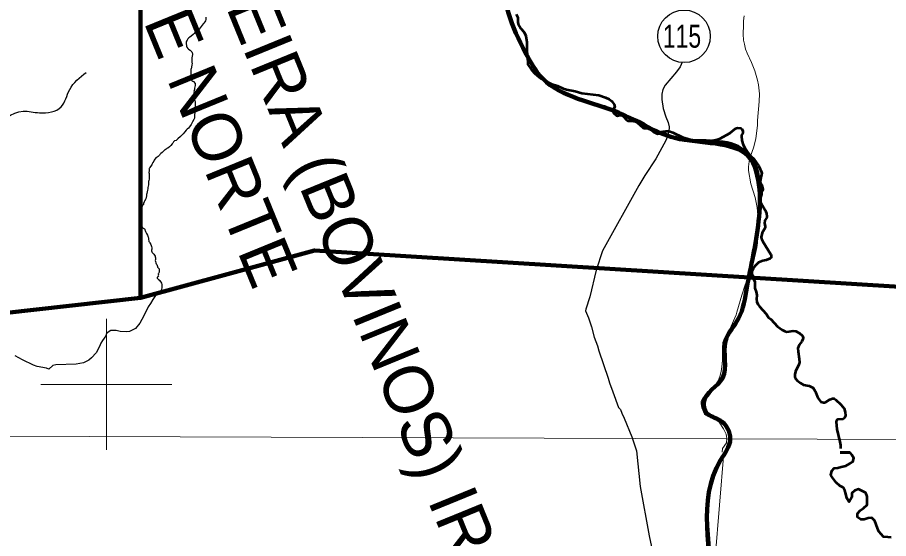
# Model space of a CAD drawing. Extents: x -1643653 to 4543381, y 1624270 to 13878484.
# Drawn here: x 748641 to 761950, y 8947643 to 8955606 of the extents above; entities that cross this region are included whole.
import ezdxf
from ezdxf.enums import TextEntityAlignment as Align

# ---------------------------------------------------------------- set-up
doc = ezdxf.new("R2010")
doc.units = 0
doc.header["$LTSCALE"] = 200
for name, color, linetype, lineweight in [('1', 7, 'Continuous', 13), ('12', 7, 'Continuous', 25), ('14', 7, 'Continuous', 13), ('2', 7, 'Continuous', 13), ('24', 7, 'Continuous', 25), ('26', 7, 'Continuous', 106), ('28', 7, 'Continuous', 53), ('48', 7, 'Continuous', 25), ('60', 7, 'Continuous', 13), ('9', 7, 'Continuous', 90)]:
    doc.layers.add(name, color=color, linetype=linetype, lineweight=lineweight)
doc.layers.add('42', color=7, linetype='Continuous')

msp = doc.modelspace()

# ---------------------------------------------------------------- linework, layer by layer
at = {"layer": '1'}
msp.add_line((565315.3, 8949866.8), (791497.7, 8949052.2), dxfattribs=at)
at = {"layer": '12'}
msp.add_line((757384.6, 8951334.8), (757323.5, 8951149.2), dxfattribs=at)
for points in [[(758795.3, 8954919.8), (758763.7, 8954849.6), (758709.9, 8954774.5), (758538.4, 8954573), (758503, 8954502.6), (758484, 8954433.8), (758484.1, 8954352.4), (758508.3, 8954214.7), (758549.7, 8954085.3), (758582.8, 8954000), (758600.3, 8953935.2), (758599.5, 8953906.9), (758576.1, 8953802), (758547.2, 8953725.3), (758396.4, 8953446.5), (758226.2, 8953190.3), (758132.7, 8953038)], [(758132.7, 8953038), (757580.3, 8952039.8), (757484.9, 8951743.2), (757384.6, 8951334.8)], [(757323.5, 8951149.2), (757320.3, 8951125.5), (757364.2, 8951016.5), (757410.7, 8950881), (757454.7, 8950719.9), (757502.3, 8950586.3), (757524.8, 8950509.5), (757666, 8950096.7), (757688, 8950021.8), (757738.6, 8949883.5)], [(757738.6, 8949883.5), (757825.6, 8949645.7), (757854.2, 8949615), (757875.3, 8949559.4), (757912.7, 8949482.2), (758025.8, 8949198.1), (758100.6, 8948982.2)], [(758100.6, 8948982.2), (758153.1, 8948438), (758293, 8947683.8), (758328, 8947515.6), (758414, 8947347.3), (758520, 8947087.3), (758641.6, 8946898.6), (758763.3, 8946740.5), (758961.1, 8946495.6), (759108.2, 8946327.2), (759473.4, 8945893.6), (759814, 8945575.9), (759907.3, 8945497.2), (759983.7, 8945452)]]:
    msp.add_lwpolyline(points, dxfattribs=at)
at = {"layer": '12', "lineweight": 40}
msp.add_spline([(761549.2, 8957020.4), (762383.1, 8955993.9), (763257, 8954902.9), (764214.4, 8953717.3), (766168.2, 8951324.4), (767086.6, 8950171.6), (770317.8, 8946184.2), (771971, 8944146), (773006.3, 8942876.2), (773223.4, 8942642.3), (773373.7, 8942274.8), (774008.3, 8940921.5), (774359, 8940136.3), (774475.8, 8939919.1), (774642.8, 8939785.5), (774893.3, 8939668.5), (775511.2, 8939484.7), (775928.6, 8939267.5), (776078.9, 8939184), (776379.5, 8938916.7), (776680.1, 8938749.6), (776830.4, 8938582.6), (777398.1, 8938348.7), (777899.1, 8938231.7), (778550.4, 8938482.3), (779134.8, 8938866.6), (779452.1, 8939250.8), (779569, 8939384.5), (779685.9, 8939351.1), (779852.9, 8939217.4), (780086.7, 8939217.4), (780604.3, 8939451.3), (781055.2, 8939618.4), (781439.3, 8939618.4), (781823.3, 8939518.1), (782090.5, 8939401.2), (782290.9, 8939367.8), (782524.7, 8939518.1), (782858.7, 8939618.4), (783192.6, 8939651.8), (783509.9, 8939818.9), (783910.7, 8940119.6), (784278.1, 8940336.8), (784625.2, 8940434.5)], degree=3, dxfattribs=at)
at = {"layer": '14'}
for points in [[(759741.8, 8955628.8), (759734.4, 8955555.9), (759735.8, 8955487.2), (759729.9, 8955349.5), (759736.2, 8955258.9), (759747.1, 8955195), (759765.6, 8955122.1), (759788.1, 8955057.4), (759856.1, 8954919.7), (759906.8, 8954790.2), (759947.4, 8954648.7), (759961.4, 8954575.8), (759976.4, 8954438.3), (759973.9, 8954322.7), (759947.5, 8954029.8), (759946, 8953952.7), (759923.2, 8953754.8), (759889.6, 8953629.9), (759834.2, 8953471.3), (759819.5, 8953402.5), (759811.3, 8953325.1), (759812.4, 8953265), (759848.2, 8953062.8), (759909.9, 8952856.4), (759942.4, 8952701.7), (759952.9, 8952580.2), (759946.5, 8952160.2), (759939.3, 8952091.6), (759880.8, 8951841.8), (759807.5, 8951640.4), (759753.1, 8951507.3), (759709.3, 8951360.8)], [(759709.3, 8951360.8), (759632, 8951102.5), (759624.2, 8951061.5), (759522.6, 8950843.3), (759474.2, 8950762.9), (759445.5, 8950706.2), (759419.9, 8950637.9), (759411.1, 8950557.2), (759411.4, 8950380.3), (759406.8, 8950307.6), (759392.1, 8950195), (759374.3, 8950118.4), (759344.4, 8950054), (759304, 8949993.2), (759170.9, 8949865.1), (759105.4, 8949780.7), (759086.2, 8949743.5), (759087.4, 8949705.1), (759098.4, 8949641.2), (759121.3, 8949577.4), (759137.2, 8949545.1), (759155.9, 8949527), (759216.2, 8949497.1), (759288.5, 8949470.6), (759360.2, 8949422), (759430.6, 8949317.8), (759467.5, 8949241.1), (759477.5, 8949172.3), (759475.1, 8949104), (759414.6, 8949021.4), (759409.5, 8948961.3)], [(759300.4, 8947350.8), (759434.4, 8948959.2)]]:
    msp.add_lwpolyline(points, dxfattribs=at)
at = {"layer": '2'}
for p, q in [((750000, 8949000), (750000, 8951000)), ((749000, 8950000), (751000, 8950000))]:
    msp.add_line(p, q, dxfattribs=at)
at = {"layer": '24', "lineweight": 53}
for p, q in [((761210.9, 8948956.2), (761361.4, 8948961.1)), ((761361.4, 8948961.1), (761210.9, 8948956.2))]:
    msp.add_line(p, q, dxfattribs=at)
for points in [[(756259.8, 8955654.5), (756286.7, 8955604.2), (756288.2, 8955533), (756292.5, 8955510.1), (756334.1, 8955437.5), (756380.4, 8955379.2), (756407.6, 8955324), (756421.1, 8955229.4), (756423.2, 8955087.5), (756434.1, 8955015.4), (756438.6, 8954889.2), (756493.2, 8954806.4), (756538.7, 8954753.6), (756587.5, 8954711), (756633.8, 8954677.4), (756743.5, 8954615), (756793.6, 8954592.1), (756890.4, 8954560.2), (756980.7, 8954519.9), (757031, 8954506.2), (757164, 8954481.5), (757264.8, 8954446.9), (757524.6, 8954416.7), (757626.7, 8954382.9), (757679.9, 8954358.9), (757723, 8954324.3), (757758.4, 8954274.9), (757765.6, 8954237.9), (757739.5, 8954184.8), (757736.2, 8954171.3), (757757.5, 8954135.5), (757791.8, 8954108), (757806.3, 8954104.2), (757824.5, 8954106), (757844.9, 8954115.1), (757869, 8954113.3), (757902.6, 8954091.2), (757943.8, 8954043.1), (757966.1, 8954024.2), (758029.9, 8954025.6), (758085, 8954017.8), (758101.3, 8954008.5)], [(758101.3, 8954008.5), (758106.9, 8953999.7), (758199.7, 8953917.6), (758218.4, 8953912.5), (758277.7, 8953907), (758325.5, 8953888.4), (758361.3, 8953858.8), (758419, 8953828.6), (758444.5, 8953830.4), (758487.6, 8953856), (758504.7, 8953862.3), (758544.9, 8953868.4), (758596.1, 8953866.1), (758654.8, 8953849.9), (758801, 8953777.3), (759008.6, 8953716.3), (759048.5, 8953710.9), (759118.3, 8953710.2), (759284.1, 8953730.2), (759331.6, 8953739.6), (759379.3, 8953754.1), (759522.6, 8953839.4), (759613.7, 8953910.2), (759644.3, 8953919), (759693.9, 8953913.5), (759706.3, 8953902.4), (759724.5, 8953867.6), (759724, 8953840.1), (759705.2, 8953806.7), (759701.8, 8953791.3), (759706.6, 8953728), (759727, 8953657.3), (759757.2, 8953601.2), (759799.2, 8953541), (759851.7, 8953481.5), (759893.5, 8953445.3), (759965.3, 8953342.1)], [(759965.3, 8953342.1), (759970.4, 8953332.8), (760015.5, 8953230.4), (759993.3, 8953133.4), (759989.8, 8953090.2), (759995.2, 8953072.2), (760012.7, 8953041.9), (760030.5, 8952976.2), (760028.6, 8952967.7), (760010.5, 8952941.3), (760006.7, 8952900.2), (759980.5, 8952814.3), (760064.6, 8952661.4), (760083.7, 8952610.4), (760092.8, 8952563.5), (760088.5, 8952550.5), (760057.5, 8952502.3), (760057.1, 8952461.6), (760064.8, 8952411), (760063.1, 8952393.2), (760019.9, 8952313.4), (760004.7, 8952250.6), (760010.5, 8952223.1), (760028.2, 8952180.1), (760153.6, 8951982.2), (760158.8, 8951968.6), (760154.4, 8951934.5), (760142.6, 8951924.2), (760078.6, 8951897.8), (760029, 8951887.2), (759964.9, 8951861.7), (759906.3, 8951805.3), (759880.4, 8951769.2), (759863.6, 8951724.3), (759860.3, 8951690), (759879.4, 8951623.6), (759905.1, 8951565), (759908.9, 8951466.9), (759927.6, 8951412), (759938.9, 8951364.3), (759933.3, 8951303), (759936.8, 8951260.5), (759955, 8951224.7), (759979.8, 8951190.2), (760080.6, 8951077.7), (760114.7, 8951023.7), (760149.7, 8950995.8), (760252.8, 8950886), (760322.7, 8950833.4), (760366, 8950810.2), (760393.2, 8950802.8), (760433.7, 8950805.5), (760491.5, 8950816), (760531.6, 8950814.5), (760588.5, 8950783.7), (760628.4, 8950748.2), (760642.2, 8950730.7), (760646.4, 8950707.4), (760641.5, 8950688.1), (760625.4, 8950655), (760584.9, 8950602), (760566, 8950552.7), (760567.4, 8950502.1), (760585.6, 8950389.3), (760588.6, 8950335.2)], [(760588.6, 8950335.2), (760579.4, 8950302.6), (760526.2, 8950197.8), (760517.9, 8950150.9), (760518.6, 8950115), (760524.8, 8950096.2), (760560.2, 8950052.5), (760573.6, 8950045.6), (760600.4, 8950021.6), (760652.6, 8949994.7), (760735.2, 8949978.4), (760796.3, 8949944.7), (760827, 8949897.8), (760870.5, 8949794.4), (760894.4, 8949756.4), (760917.9, 8949733), (760957.7, 8949723.4), (760983.8, 8949723)], [(760983.8, 8949723), (761052.1, 8949768.5), (761052.1, 8949768.5), (761093.2, 8949782.5), (761118.7, 8949782.5), (761143, 8949765.5), (761222.5, 8949692), (761270.1, 8949631.4), (761287.7, 8949575), (761290.9, 8949523.6), (761283.1, 8949497.5), (761268.7, 8949478.8), (761253.4, 8949469.9), (761168.1, 8949460.9), (761157.1, 8949449.3), (761149.4, 8949429.2), (761159.4, 8949316.6), (761205.6, 8949123.6), (761214.3, 8949072.6), (761216.9, 8949017.9)], [(761987.8, 8947662.2), (761936.9, 8947662.5), (761870.9, 8947668), (761835.5, 8947709), (761800.2, 8947750), (761780.2, 8947801), (761760.3, 8947857.2), (761740.3, 8947913.3), (761694.9, 8947959.5), (761638.9, 8947954.7), (761577.7, 8947934.7), (761526.9, 8947935), (761476.3, 8947971), (761476.6, 8948027), (761517.6, 8948072.6), (761568.7, 8948107.9), (761625, 8948158.5), (761625.5, 8948219.6), (761620.8, 8948285.9), (761600.9, 8948342), (761489.4, 8948398.8), (761433.3, 8948378.7), (761387.2, 8948338.3), (761386.8, 8948277.2), (761350.7, 8948206.1), (761310.4, 8948262.3), (761295.6, 8948328.7), (761280.7, 8948379.7), (761255.6, 8948425.7), (761204.9, 8948451.5), (761149.3, 8948502.7), (761098.9, 8948564.2), (761068.7, 8948610.2), (761084.4, 8948676.3), (761120.3, 8948716.8), (761176.3, 8948726.7), (761227.3, 8948741.7), (761298.6, 8948756.5), (761359.8, 8948791.8), (761405.8, 8948816.9), (761421.4, 8948872.9), (761391.3, 8948924), (761361.4, 8948961.1)]]:
    msp.add_lwpolyline(points, dxfattribs=at)
at = {"layer": '24'}
for points in [[(756259.8, 8955654.5), (756286.7, 8955604.2), (756288.2, 8955533), (756292.5, 8955510.1), (756334.1, 8955437.5), (756380.4, 8955379.2), (756407.6, 8955324), (756421.1, 8955229.4), (756423.2, 8955087.5), (756434.1, 8955015.4), (756438.6, 8954889.2), (756493.2, 8954806.4), (756538.7, 8954753.6), (756587.5, 8954711), (756633.8, 8954677.4), (756743.5, 8954615), (756793.6, 8954592.1), (756890.4, 8954560.2), (756980.7, 8954519.9), (757031, 8954506.2), (757164, 8954481.5), (757264.8, 8954446.9), (757524.6, 8954416.7), (757626.7, 8954382.9), (757679.9, 8954358.9), (757723, 8954324.3), (757758.4, 8954274.9), (757765.6, 8954237.9), (757739.5, 8954184.8), (757736.2, 8954171.3), (757757.5, 8954135.5), (757791.8, 8954108), (757806.3, 8954104.2), (757824.5, 8954106), (757844.9, 8954115.1), (757869, 8954113.3), (757902.6, 8954091.2), (757943.8, 8954043.1), (757966.1, 8954024.2), (758029.9, 8954025.6), (758085, 8954017.8), (758101.3, 8954008.5)], [(751521.3, 8955611.7), (751519.4, 8955598.1), (751518.8, 8955572), (751514.3, 8955556), (751506.3, 8955540.3), (751487.9, 8955518.6), (751476.7, 8955507.2), (751464.3, 8955487.1), (751446.1, 8955465), (751433, 8955446.6), (751417.1, 8955424.3), (751410.1, 8955416.6), (751379.8, 8955399.5), (751358.3, 8955381.5), (751341.1, 8955360.8), (751323.2, 8955344.1), (751293.9, 8955319.6), (751275.7, 8955305.3), (751259.5, 8955292.8), (751245.4, 8955280.6), (751231.7, 8955260.9), (751222.1, 8955244), (751218, 8955227.8), (751219.2, 8955211.1)], [(751219.2, 8955211.1), (751223.8, 8955165.8), (751229.9, 8955150.6), (751245.2, 8955131.5), (751254.7, 8955121.9), (751279.2, 8955106.3), (751297.5, 8955088.6), (751302.9, 8955080.6), (751310.3, 8955065.4), (751314.1, 8955055.2), (751314.7, 8955041.2), (751310.3, 8955015.7), (751307.7, 8954988.5), (751305.8, 8954937.9), (751306.7, 8954916), (751309.1, 8954905.5)], [(751309.1, 8954905.5), (751307.7, 8954878.1), (751301.9, 8954853), (751298.4, 8954837.1), (751293.7, 8954825), (751291.3, 8954811.7), (751288.5, 8954774.2), (751288.8, 8954720.4), (751288.8, 8954687.3), (751290.7, 8954677.2), (751300.6, 8954649.5), (751305.3, 8954642.5), (751318.4, 8954633.2), (751328.3, 8954627.8), (751332.1, 8954625.3)], [(751332.1, 8954625.3), (751355.9, 8954594), (751356.8, 8954581.6), (751355, 8954566), (751346.2, 8954527.5), (751344.9, 8954505.5), (751340.3, 8954487.1), (751337.9, 8954474.9), (751339.8, 8954461.6), (751337.9, 8954450.2), (751330.1, 8954423.6), (751328.8, 8954408.9), (751329.7, 8954399.3), (751334.7, 8954381.9), (751338, 8954365.6), (751347.6, 8954346.8), (751351.8, 8954334.4), (751355.4, 8954314.7), (751356.3, 8954289.5), (751358.6, 8954221.4), (751360.5, 8954199.8), (751358.2, 8954173.9), (751344.9, 8954124.4), (751343.9, 8954113), (751346.9, 8954083.7), (751343.8, 8954066), (751335.8, 8954047.5), (751314.9, 8954010.9), (751294.9, 8953971.7), (751270.3, 8953935.2), (751255.4, 8953915.8), (751235.4, 8953897.9), (751217.2, 8953882.7), (751198.8, 8953859.8), (751170.9, 8953825.3), (751131.4, 8953785.2), (751091.2, 8953752.8), (751063.4, 8953728), (751042, 8953718.8), (751024.7, 8953707.5)], [(758101.3, 8954008.5), (758106.9, 8953999.7), (758199.7, 8953917.6), (758218.4, 8953912.5), (758277.7, 8953907), (758325.5, 8953888.4), (758361.3, 8953858.8), (758419, 8953828.6), (758444.5, 8953830.4), (758487.6, 8953856), (758504.7, 8953862.3), (758544.9, 8953868.4), (758596.1, 8953866.1), (758654.8, 8953849.9), (758801, 8953777.3), (759008.6, 8953716.3), (759048.5, 8953710.9), (759118.3, 8953710.2), (759284.1, 8953730.2), (759331.6, 8953739.6), (759379.3, 8953754.1), (759522.6, 8953839.4), (759613.7, 8953910.2), (759644.3, 8953919), (759693.9, 8953913.5), (759706.3, 8953902.4), (759724.5, 8953867.6), (759724, 8953840.1), (759705.2, 8953806.7), (759701.8, 8953791.3), (759706.6, 8953728), (759727, 8953657.3), (759757.2, 8953601.2), (759799.2, 8953541), (759851.7, 8953481.5), (759893.5, 8953445.3), (759965.3, 8953342.1)], [(751024.7, 8953707.5), (751020.7, 8953696.5), (751014.4, 8953686.1), (751006.4, 8953674.5), (750985.2, 8953648.4)], [(750896.8, 8953584.2), (750886.7, 8953576), (750873.8, 8953563.7), (750863.4, 8953552.2), (750852.4, 8953541.5), (750833.6, 8953527.6), (750825.1, 8953520.3), (750818.7, 8953513.5), (750809.7, 8953502.3), (750797.1, 8953486.9), (750789.7, 8953478.8), (750777, 8953472.5), (750766.3, 8953466.8), (750757.3, 8953459.3), (750746.6, 8953446.4), (750741, 8953438.2), (750731.8, 8953423.6), (750723, 8953408.8), (750711.5, 8953388.1), (750700.2, 8953366.8), (750692.9, 8953354.2), (750675.2, 8953329.8), (750661.4, 8953311.1), (750656.3, 8953301.1), (750655, 8953296.7), (750651.6, 8953278.5), (750651.3, 8953261.4), (750650.2, 8953238.4), (750651.3, 8953219.6), (750653.3, 8953204.2), (750654.4, 8953182.6), (750655, 8953161.3), (750652.1, 8953137.2), (750647.9, 8953115.3), (750645.7, 8953100.4), (750643.2, 8953069.9), (750641.5, 8953049.7), (750633.6, 8953006.2), (750631.9, 8952984.9), (750628.5, 8952968.8), (750621.2, 8952943.5), (750616.2, 8952913.3), (750614.2, 8952902.7), (750612.8, 8952878.8), (750609.7, 8952855.8), (750602.6, 8952835.1), (750584.1, 8952800.1), (750578.5, 8952788.3), (750568.9, 8952760.9), (750564.4, 8952748), (750558.2, 8952739), (750552.9, 8952730.9), (750545.3, 8952719.9), (750536.8, 8952704.9), (750529.8, 8952688.7), (750523.1, 8952676.6), (750513.8, 8952662.3), (750506, 8952639.1), (750499.5, 8952623.1), (750495.6, 8952609.9), (750494.2, 8952597), (750494.2, 8952587.5), (750496.7, 8952581), (750498.4, 8952577.1), (750515, 8952523.4)], [(750986.8, 8953648.3), (750985.4, 8953646.6), (750979.8, 8953643), (750972.5, 8953637.9), (750963.2, 8953629.5), (750940.5, 8953610.7), (750922.4, 8953602.4), (750911.4, 8953595.1), (750896.8, 8953584.2)], [(759965.3, 8953342.1), (759970.4, 8953332.8), (760015.5, 8953230.4), (759993.3, 8953133.4), (759989.8, 8953090.2), (759995.2, 8953072.2), (760012.7, 8953041.9), (760030.5, 8952976.2), (760028.6, 8952967.7), (760010.5, 8952941.3), (760006.7, 8952900.2), (759980.5, 8952814.3), (760064.6, 8952661.4), (760083.7, 8952610.4), (760092.8, 8952563.5), (760088.5, 8952550.5), (760057.5, 8952502.3), (760057.1, 8952461.6), (760064.8, 8952411), (760063.1, 8952393.2), (760019.9, 8952313.4), (760004.7, 8952250.6), (760010.5, 8952223.1), (760028.2, 8952180.1), (760153.6, 8951982.2), (760158.8, 8951968.6), (760154.4, 8951934.5), (760142.6, 8951924.2), (760078.6, 8951897.8), (760029, 8951887.2), (759964.9, 8951861.7), (759906.3, 8951805.3), (759880.4, 8951769.2), (759863.6, 8951724.3), (759860.3, 8951690), (759879.4, 8951623.6), (759905.1, 8951565), (759908.9, 8951466.9), (759927.6, 8951412), (759938.9, 8951364.3), (759933.3, 8951303), (759936.8, 8951260.5), (759955, 8951224.7), (759979.8, 8951190.2), (760080.6, 8951077.7), (760114.7, 8951023.7), (760149.7, 8950995.8), (760252.8, 8950886), (760322.7, 8950833.4), (760366, 8950810.2), (760393.2, 8950802.8), (760433.7, 8950805.5), (760491.5, 8950816), (760531.6, 8950814.5), (760588.5, 8950783.7), (760628.4, 8950748.2), (760642.2, 8950730.7), (760646.4, 8950707.4), (760641.5, 8950688.1), (760625.4, 8950655), (760584.9, 8950602), (760566, 8950552.7), (760567.4, 8950502.1), (760585.6, 8950389.3), (760588.6, 8950335.2)], [(750515, 8952523.4), (750516.1, 8952514.7), (750516.4, 8952504.2), (750518.4, 8952485.1), (750519.2, 8952467.4), (750521.2, 8952458.4), (750526.2, 8952448.3), (750532.1, 8952434.9), (750535, 8952426.5), (750547.7, 8952403.8), (750555.5, 8952392.9), (750564.2, 8952385.3), (750580.2, 8952377.7), (750583.9, 8952374.9), (750585.9, 8952371.3), (750589, 8952358.9), (750592.7, 8952348.4), (750597.7, 8952335.7), (750609.2, 8952316.9), (750613.7, 8952307.1), (750626.7, 8952281), (750632.6, 8952265.7), (750637.1, 8952247.5), (750641, 8952237.3), (750645.2, 8952220.8)], [(750645.2, 8952220.8), (750650.6, 8952184.7), (750651.7, 8952177.7), (750656.5, 8952174.6), (750660.4, 8952170.1), (750663.8, 8952162), (750677.3, 8952136), (750689.4, 8952105.4), (750695.3, 8952086.9), (750695.3, 8952078.5), (750693, 8952066.5), (750687.7, 8952052), (750687.7, 8952040.5), (750693.9, 8952026.7), (750700.9, 8952015.8), (750713.9, 8951999.9), (750722.3, 8951988.1), (750733, 8951973.2), (750743.9, 8951957.8), (750747.3, 8951948.8), (750748.7, 8951932.1), (750748.1, 8951908.8), (750747, 8951893.1), (750751, 8951876.4), (750756.3, 8951858.5), (750761.9, 8951842.2), (750770.9, 8951828.7), (750777.7, 8951814.1), (750779.7, 8951800.5), (750783, 8951789.8), (750788.7, 8951782.5), (750799.9, 8951771.3), (750805.5, 8951762.6), (750807.5, 8951755.9), (750806.1, 8951746.1), (750804.6, 8951730.5), (750804.6, 8951720.1), (750805.5, 8951713.9), (750795.7, 8951694), (750793.1, 8951689.2), (750793.1, 8951685), (750794.2, 8951678.3), (750794.2, 8951671.6), (750792.6, 8951660.4), (750794.2, 8951655.1), (750793.7, 8951651.7), (750785, 8951644.2), (750776.3, 8951637.1), (750775.4, 8951629.6), (750776.6, 8951623.4), (750779.9, 8951616.9), (750784.4, 8951612.2), (750793.1, 8951606.6), (750801.1, 8951600.5), (750808.4, 8951589), (750812.6, 8951585.6), (750814.9, 8951584.1)], [(750816.8, 8951585.2), (750841.2, 8951547.4), (750845.2, 8951526.5), (750845.3, 8951483.2), (750840.6, 8951445.4), (750835.5, 8951431.8), (750782.1, 8951389.9), (750747.8, 8951356.2), (750707.5, 8951297.9), (750673.1, 8951235.5), (750638.2, 8951183.6), (750572.6, 8951045), (750509.5, 8950935), (750444.8, 8950855.3), (750395, 8950825.3), (750352, 8950806.8), (750301.3, 8950803.8), (750210.4, 8950807.4), (750148.2, 8950821.9), (750091, 8950824.7), (750065.3, 8950821.8), (750040.7, 8950809.2), (750002.6, 8950778.6), (749989.8, 8950743.1), (749940.4, 8950671.8), (749917, 8950629.2), (749893.7, 8950575.8), (749841.7, 8950483.1), (749773.8, 8950404.3), (749730.5, 8950368.5), (749651.5, 8950328), (749536, 8950306.5), (749226.3, 8950300.4), (749179.3, 8950285.4), (749120.6, 8950234.1)], [(749120.6, 8950234.1), (749082.8, 8950244.7), (748944.7, 8950271.7), (748885.6, 8950293.6), (748719.8, 8950372.3), (748606.6, 8950436)], [(760588.6, 8950335.2), (760579.4, 8950302.6), (760526.2, 8950197.8), (760517.9, 8950150.9), (760518.6, 8950115), (760524.8, 8950096.2), (760560.2, 8950052.5), (760573.6, 8950045.6), (760600.4, 8950021.6), (760652.6, 8949994.7), (760735.2, 8949978.4), (760796.3, 8949944.7), (760827, 8949897.8), (760870.5, 8949794.4), (760894.4, 8949756.4), (760917.9, 8949733), (760957.7, 8949723.4), (760983.8, 8949723)], [(760983.8, 8949723), (761052.1, 8949768.5), (761052.1, 8949768.5), (761093.2, 8949782.5), (761118.7, 8949782.5), (761143, 8949765.5), (761222.5, 8949692), (761270.1, 8949631.4), (761287.7, 8949575), (761290.9, 8949523.6), (761283.1, 8949497.5), (761268.7, 8949478.8), (761253.4, 8949469.9), (761168.1, 8949460.9), (761157.1, 8949449.3), (761149.4, 8949429.2), (761159.4, 8949316.6), (761205.6, 8949123.6), (761214.3, 8949072.6), (761216.9, 8949017.9)]]:
    msp.add_lwpolyline(points, dxfattribs=at)
msp.add_spline([(746320.5, 8952725.9), (746386.2, 8952936.5), (746754.7, 8953055.1), (747110, 8953226.2), (747465.2, 8953450.1), (747715.3, 8953581.7), (748044.2, 8953739.7), (748241.6, 8953884.6), (748728.5, 8954174.2), (748978.5, 8954147.9), (749307.5, 8954240.1), (749439.1, 8954503.4), (749689.1, 8954766.8)], degree=3, dxfattribs=at)
at = {"layer": '26'}
msp.add_spline([(738865.3, 8967422.1), (739557.2, 8967298.3), (740701.8, 8967013.8), (741413.3, 8966731.2), (743000.3, 8965872.6), (743559.1, 8965590.5), (744439.9, 8965968.4), (745374, 8966727.6), (746233.2, 8967779.5), (746809, 8968247.7), (747844.5, 8968942.9), (749056.2, 8969268.5), (750229.7, 8969581.6), (752050.8, 8969574.1), (752518.4, 8968949.1), (753046.2, 8967700.6), (754351.7, 8964009.2), (754013.3, 8962799.9), (754158.3, 8961590.6), (754279.2, 8959994.3), (754448.4, 8958857.5), (755069.1, 8957779.3), (755600.9, 8957368.1), (756072.3, 8957077.8), (756075.9, 8956332), (756399.8, 8955071.7), (756665.8, 8954671.3), (757824.9, 8954152.2), (758684.7, 8953765.2), (759807.2, 8953486.2), (759964.3, 8952494.5), (759785.3, 8951475.9), (759658.7, 8951007.7), (759460.5, 8950660.7), (759411.1, 8950095.7), (759130.3, 8949726.7), (759168.8, 8949567), (759377.9, 8949449), (759532.1, 8949168), (759383.5, 8948839.9), (759243.4, 8946764.2), (759236.6, 8946560.6)], degree=3, dxfattribs=at)
at = {"layer": '28'}
msp.add_lwpolyline([(758151.3, 8954018.2), (757631.5, 8954235.9), (757632.6, 8954238.4)], dxfattribs=at)
for points in [[(757632.6, 8954238.4), (756665.8, 8954671.3), (756399.8, 8955071.7), (756075.9, 8956332), (756072.3, 8957077.8), (755600.9, 8957368.1), (755069.1, 8957779.3), (754448.4, 8958857.5), (754422.8, 8958978.7)], [(759620.3, 8946005.2), (759236.6, 8946560.6), (759243.4, 8946764.2), (759383.5, 8948839.9), (759532.1, 8949168), (759377.9, 8949449), (759168.8, 8949567), (759130.3, 8949726.7), (759411.1, 8950095.7), (759460.5, 8950660.7), (759658.7, 8951007.7), (759785.3, 8951475.9), (759976.4, 8952615.4), (759698.4, 8953607.1), (758684.7, 8953765.2), (758151.3, 8954018.2)]]:
    msp.add_spline(points, degree=3, dxfattribs=at)
at = {"layer": '48'}
msp.add_circle((758825.5, 8955317.1), 401.3, dxfattribs=at)
at = {"layer": '60', "lineweight": 25}
msp.add_spline([(814781, 9009175.5), (814787.2, 9009173.4), (814796.9, 9009173.4), (814799.4, 9009172.4), (814805.1, 9009174.5), (814805.6, 9009176.5), (814811.7, 9009179.5), (814811.7, 9009179.5), (814801.5, 9009181), (814790.7, 9009181.5), (814784.1, 9009183.1), (814777.4, 9009185.1), (814778.4, 9009175.5)], degree=3, dxfattribs=at)
at = {"layer": '9'}
for points in [[(737921.5, 8948812.5), (740981.3, 8950253.8), (750519.5, 8951321.2), (750521.5, 8957798.6)], [(750519.5, 8951321.2), (753181.6, 8952045.1), (767371, 8951165.8), (772338.7, 8947456.5)]]:
    msp.add_lwpolyline(points, dxfattribs=at)
msp.add_spline([(779358.3, 8951316.5), (778152, 8950383.2), (776870.5, 8948893), (775858.2, 8948102.8), (775096.9, 8948098.3), (774081.6, 8948143.1), (772814, 8947781.5), (772105.2, 8947296.6), (771547.4, 8947166.9), (771322, 8946330.6), (771374.4, 8945875.5), (771395.1, 8945546.1), (769593.3, 8944681.6), (768541.6, 8943918.8), (767488.3, 8942812.2), (766189.2, 8941452.3), (765366.7, 8940769), (764084.5, 8940646.2), (763321.5, 8941097.2), (762890.2, 8941044.2), (762866.3, 8940639.2), (762461.9, 8940181.4), (761397.4, 8939821), (760940.2, 8939919.5), (760875, 8939930.2)], degree=3, dxfattribs=at)

# ---------------------------------------------------------------- texts
at = {"layer": '42'}
for s, p in [('FRUTICULTURA E FORRAGEIRA (BOVINOS) IRRIGADA', (751782.1, 8955862.9)), ('AGRESTE NORTE', (750625, 8955389.9))]:
    msp.add_text(s, height=750, rotation=292.237, dxfattribs=at).set_placement(p, align=Align.CENTER)
at = {"layer": '48', "width": 0.75}
msp.add_text('115', height=350, dxfattribs=at).set_placement((758793.9, 8955143.8), align=Align.CENTER)

doc.saveas('drawing.dxf')
